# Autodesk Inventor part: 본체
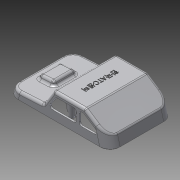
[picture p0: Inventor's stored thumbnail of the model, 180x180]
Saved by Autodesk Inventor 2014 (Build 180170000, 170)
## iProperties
Created: 2015-05
Part Number: 본체
Material: ABS 플라스틱
Document SubType Name: Modeling
Designer: Administrator
Density: 1.06 g/cm^3
Appearance: 매끄러움 - 흰색
Mass: 35.782 g
Surface Area: 333.401 cm^2
Volume: 33.7566 cm^3
Author: Administrator
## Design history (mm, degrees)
sketch "스케치1"
  geometry: L1 (61, 0)-(-61, 0); L2 (-61, 0)-(-61, 30); L3 (-61, 30)-(19, 30); L4 (19, 10.201)-(61, 8); L5 (61, 8)-(61, 0); L6 (19, 30)-(19, 10.201); 2 further points
  constraints: 12 end point, 2 parallel, 2 perpendicular, 1 coincident, 1 horizontal, 1 midpoint
  dimensions: "d0" = 122 distance of L1.end L1.start; "d2" = 30 distance of L1.end L2.end; "d4" = 3 deg angle of L1 L4; "d5" = 8 distance of L4.end L1.start; "d6" = 80 distance of L2.end L3.end
extrude "돌출1" new body sketch "스케치1" stored distance "d7" = 76; taper "d8" = 0 deg
sketch "스케치2"
  geometry: L1 (61, 0)-(61, 30) reference; L2 (61, 30)-(-19, 30) reference; L3 (31, 30)-(61, 10); 1 further point
  constraints: 2 end point, 2 point on line
  dimensions: "d9" = 20 vertical distance of L3.start L3.end; "d10" = 30 horizontal distance of L3.start L3.end
extrude "돌출2" cut sketch "스케치2" stored distance "d11" = 76; taper "d12" = 0 deg
sketch "스케치3"
  geometry: L1 (61, 10)-(31, 30) reference; L2 (-61, 0)-(61, 0) reference; L3 (61, 0)-(61, 10) reference; L4 (57.738, 12.175)-(61, 0); 1 further point
  constraints: 2 end point, 1 point on line
  dimensions: "d13" = 105 deg angle of L2 L4
extrude "돌출3" cut sketch "스케치3" stored distance "d14" = 76; taper "d15" = 0 deg
sketch "스케치4"
  geometry: L1 (31, 30)-(-19, 30) reference; L2 (-19, 30)-(-19, 10.201) reference; L3 (-19, 10.201)-(-61, 8) reference; L4 (-19, 10.201)-(-6.628, 30); 1 further point
  constraints: 2 end point, 1 point on line
  dimensions: "d16" = 125 deg angle of L3 L4
extrude "돌출4" cut sketch "스케치4" stored distance "d17" = 76; taper "d18" = 0 deg
sketch "스케치5"
  geometry: L1 (-19, 10.201)-(-61, 8) reference; L2 (-50, 8.576)-(-48.471, 13.576); L3 (-48.471, 13.576)-(-32.122, 14.625); L4 (-32.122, 14.625)-(-30, 9.625); 1 further point
  constraints: 6 end point, 2 point on line
  dimensions: "d19" = 70 deg angle of L1 L4; "d20" = 70 deg angle of L1 L2; "d21" = 20 horizontal distance of L4.end L2.start; "d22" = 5 vertical distance of L2.start L2.end; "d23" = 5 vertical distance of L3.end L4.end; "d24" = 11 horizontal distance of L1.end L2.start
extrude "돌출5" join sketch "스케치5" distance "d25" = 76; taper "d26" = 0 deg
sketch "스케치6"
  geometry: L1 (-30, 9.625)-(-32.122, 14.625) reference; L2 (-32.122, 14.625)-(-48.471, 13.576) reference; L3 (-48.471, 13.576)-(-50, 8.576) reference; L4 (-50, 8.576)-(-61, 8) reference; L5 (-50, 8.576)-(-30, 9.625); 1 further point
  constraints: 2 end point, 1 collinear
extrude "돌출6" cut sketch "스케치6" distance "d27" = 25; taper "d28" = 0 deg
sketch "스케치7"
  geometry: L1 (-19, 10.201)-(-61, 8) reference; L2 (-61, 8)-(-61, 0) reference; L3 (-61, 0)-(61, 0) reference; L4 (-61, 0)-(-58.826, 8.114); 1 further point
  constraints: 2 end point, 1 point on line
  dimensions: "d29" = 105 deg angle of L3 L4
extrude "돌출7" cut sketch "스케치7" stored distance "d30" = 25; taper "d31" = 0 deg
fillet "모깎기1" dims "d32" = 12
fillet "모깎기2" dims "d33" = 3
fillet "모깎기3" dims "d34" = 3
fillet "모깎기4" dims "d35" = 3
feature "쉘1" dims "d36" = 2
sketch "스케치8"
  geometry: L1 (-7.51, 28.59)-(-18.172, 11.526) reference; L2 (30.092, 30)-(-4.965, 30) reference; L3 (45.453, 20.365)-(31.756, 29.496) reference; L4 (-4.738, 23.59)-(-10.362, 14.59); L5 (-7.818, 10)-(17.77, 10); L6 (20.77, 13)-(20.77, 22); L7 (17.77, 25)-(-2.194, 25); L8 (23.986, 22)-(23.986, 13); L9 (26.986, 10)-(42.078, 10); L10 (26.986, 25)-(28.578, 25); L11 (30.242, 24.496)-(43.742, 15.496); A1 r 3 centre (-2.194, 22) between (-2.194, 25) and (-4.738, 23.59); A2 r 3 centre (-7.818, 13) between (-10.362, 14.59) and (-7.818, 10); A3 r 3 centre (17.77, 13) between (17.77, 10) and (20.77, 13); A4 r 3 centre (17.77, 22) between (20.77, 22) and (17.77, 25); A5 r 3 centre (26.986, 22) between (26.986, 25) and (23.986, 22); A6 r 3 centre (26.986, 13) between (23.986, 13) and (26.986, 10); A7 r 3 centre (42.078, 13) between (42.078, 10) and (43.742, 15.496); A8 r 3 centre (28.578, 22) between (30.242, 24.496) and (28.578, 25); 7 further points
  constraints: 16 end point, 16 point on circle, 16 tangent, 12 point on line, 8 centre point, 6 equal radius, 4 parallel, 3 perpendicular
  dimensions: "d37" = 5 distance between parallel lines of L4 L1; "d38" = 5 distance between parallel lines of L2 L7; "d39" = 34 distance of point (-13.23, 10) point (20.77, 10); "d40" = 15 distance of point (20.77, 10) point (20.77, 25); "d41" = 3 radius of A1; "d44" = 15 distance of point (23.986, 25) point (23.986, 10); "d45" = 28 distance of point (23.986, 10) point (51.986, 10); "d46" = 5 distance between parallel lines of L3 L11; "d47" = 5 distance between parallel lines of L2 L10; "d48" = 3 radius of A5
extrude "돌출8" cut sketch "스케치8" stored distance "d49" = 25; taper "d50" = 0 deg
node "작업 평면1"
sketch "스케치9"
  geometry: L1 (-23, 0)-(-19, 0); L2 (-12, 0)-(-8, 0); L3 (8, 0)-(12, 0); L4 (19, 0)-(23, 0); A1 r 2 centre (-10, 0) between (-8, 0) and (-12, 0); A2 r 2 centre (-21, 0) between (-19, 0) and (-23, 0); A3 r 2 centre (10, 0) between (12, 0) and (8, 0); A4 r 2 centre (21, 0) between (23, 0) and (19, 0); A5 r 2 centre (-21, 0) between (-23, 0) and (-19, 0); A6 r 2 centre (-10, 0) between (-12, 0) and (-8, 0); A7 r 2 centre (10, 0) between (8, 0) and (12, 0); A8 r 2 centre (21, 0) between (19, 0) and (23, 0); 5 further points
  constraints: 16 point on circle, 8 centre point, 8 end point, 4 coincident, 4 horizontal alignment, 4 midpoint, 3 collinear, 1 horizontal
  dimensions: "d52" = 4 diameter of A3; "d53" = 4 diameter of A4; "d54" = 4 diameter of A1; "d55" = 4 diameter of A2; "d56" = 10 distance of A3.centre point (0, 0); "d57" = 20 distance of A3.centre A1.centre; "d58" = 11 distance of A4.centre A3.centre; "d59" = 11 distance of A1.centre A2.centre
extrude "돌출9" join sketch "스케치9" stored distance "d60" = 25; taper "d61" = 0 deg
chamfer "모따기1" distance "d62" = 1; stored, may be unused: second distance "d63" = 2, angle "d64" = 45 deg
sketch "스케치10"
  geometry: L1 (0, 0)-(97.153, 0) reference; L2 (-10.353, -64)-(-10.353, -12) reference; L3 (0, -2)-(97.153, -2) reference; L4 (107.506, -12)-(107.506, -64) reference; L5 (97.153, -74)-(0, -74) reference; L6 (97.153, -1)-(0, -1); L7 (-11.353, -12)-(-11.353, -64); L8 (0, -75)-(97.153, -75); L9 (108.506, -64)-(108.506, -12); 5 further points; 4 other entities
  constraints: 8 end point, 7 parallel, 16 other
  dimensions: "d65" = 1 distance between parallel lines of L1 L6
extrude "돌출10" join sketch "스케치10" distance "d66" = 1; taper "d67" = 0 deg
sketch "스케치11"
  geometry: L1 (-12.423, -12)-(-12.423, -64) reference; C1 r 3 at (88.577, -38); C2 r 3 at (48.577, -16); C3 r 3 at (48.577, -60); C4 r 3 at (8.577, -38); 1 further point
  constraints: 4 centre point, 2 horizontal alignment, 2 vertical alignment
  dimensions: "d68" = 6 diameter of C1; "d69" = 6 diameter of C3; "d70" = 6 diameter of C2; "d71" = 6 diameter of C4; "d91" = 40 distance of C1.centre point (48.577, -38); "d92" = 40 distance of C4.centre point (48.577, -38); "d93" = 21 distance from line of C4.centre L1 (derived); "d94" = 22 distance of C3.centre point (48.577, -38); "d95" = 44 distance of C3.centre C2.centre
extrude "돌출11" join sketch "스케치11" stored distance "d72" = 1; taper "d73" = 4 deg
node "작업 평면2"
sketch "스케치12"
  geometry: L1 (-5, 23)-(5, 23); L2 (5, 23)-(5, 21); L3 (5, 21)-(-5, 21); L4 (-5, 21)-(-5, 23); L5 (-5, 23)-(5, 21); L6 (5, 23)-(-5, 21); L7 (44.982, 1)-(34.982, 1); L8 (34.982, 1)-(34.982, -1); L9 (34.982, -1)-(44.982, -1); L10 (44.982, -1)-(44.982, 1); L11 (44.982, 1)-(34.982, -1); L12 (34.982, 1)-(44.982, -1); L13 (-5, -21)-(5, -21); L14 (5, -21)-(5, -23); L15 (5, -23)-(-5, -23); L16 (-5, -23)-(-5, -21); L17 (-5, -21)-(5, -23); L18 (5, -21)-(-5, -23); L19 (-44.786, 1)-(-34.786, 1); L20 (-34.786, 1)-(-34.786, -1); L21 (-34.786, -1)-(-44.786, -1); L22 (-44.786, -1)-(-44.786, 1); L23 (-44.786, 1)-(-34.786, -1); L24 (-34.786, 1)-(-44.786, -1); C1 r 3 at (0, 22) reference; C2 r 3 at (40, 0) reference; C3 r 3 at (0, -22) reference; C4 r 3 at (-40, 0) reference; A1 r 5.028 centre (0, 22) between (4.965, 22.79) and (4.965, 21.21) reference; A2 r 5.028 centre (0, -22) between (4.965, -21.21) and (4.965, -22.79) reference; 3 further points; 2 other entities
  constraints: 48 end point, 8 midpoint, 8 parallel, 4 horizontal, 4 perpendicular, 2 vertical alignment, 2 other
  dimensions: "d75" = 10 distance of L2.end L3.end; "d76" = 2 distance of L1.end L2.end; "d77" = 10 distance of L8.end L9.end; "d78" = 2 distance of L7.end L8.end; "d79" = 10 distance of L14.end L15.end; "d80" = 2 distance of L13.end L14.end; "d81" = 10 distance of L20.end L21.end; "d82" = 2 distance of L19.end L20.end
extrude "돌출12" join sketch "스케치12" stored distance "d83" = 1; taper "d84" = 2.5 deg
sketch "스케치13"
  geometry: L1 (0, 0)-(-1.095, 25.103) reference; L2 (-11.476, 7.847)-(-0.813, 24.895) reference; L3 (0, 0)-(-3.694, 20.948); L4 (-4.589, 26.025)-(0.035, 26.025); L5 (-1.095, 25.103)-(-3.694, 20.948); L6 (-3.694, 20.948)-(-4.589, 26.025); 5 further points; 1 other entity
  constraints: 8 end point, 2 horizontal, 2 point on line, 1 coincident, 1 parallel, 1 other
  dimensions: "d85" = 100 deg angle of L3 L4
extrude "돌출13" join sketch "스케치13" stored distance "d86" = 1; taper "d87" = 0 deg
sketch "스케치14"
  geometry: L1 (1.95, 0)-(3.085, 26.025) reference; L2 (-8.015, 25.365)-(27.042, 25.365) reference; L3 (1.95, 0)-(6.539, 26.025); L4 (3.085, 26.025)-(6.539, 26.025); 1 further point
  constraints: 4 end point, 1 parallel
  dimensions: "d88" = 100 deg angle of L4 L3
extrude "돌출14" join sketch "스케치14" stored distance "d89" = 1; taper "d90" = 0 deg
sketch "스케치16"
  geometry: L1 (2.432, -15.957)-(0.983, -16.923) reference; L2 (1.736, 0)-(2.432, -15.957) reference; L3 (1.736, 0)-(0, 0) reference; L4 (1.736, 0)-(4.55, -15.957); L5 (2.432, -15.957)-(4.55, -15.957); L6 (2.432, -15.957)-(4.327, -14.692); 3 further points
  constraints: 6 end point, 2 coincident, 1 collinear, 1 parallel, 1 point on line
  dimensions: "d99" = 100 deg angle of L5 L4
extrude "돌출16" join sketch "스케치16" stored distance "d100" = 1; taper "d101" = 0 deg
sketch "스케치17"
  geometry: L1 (1.354, -9.892)-(-0.427, -9.778) reference; L2 (0, 0)-(-0.427, -9.778) reference; L3 (0, 0)-(-2.349, -9.655); L4 (-0.427, -9.778)-(-2.349, -9.655); 1 further point
  constraints: 4 end point, 1 collinear
  dimensions: "d102" = 100 deg angle of L3 L4
extrude "돌출17" join sketch "스케치17" stored distance "d103" = 1; taper "d104" = 0 deg
sketch "스케치18"
  geometry: L1 (2.425, -10.476)-(0.606, -10.36) reference; L2 (1.968, 0)-(2.425, -10.476) reference; L3 (1.968, 0)-(3.134, -10.522); L4 (2.425, -10.476)-(3.134, -10.522); 1 further point
  constraints: 4 end point, 1 collinear
  dimensions: "d105" = 100 deg angle of L4 L3
extrude "돌출18" join sketch "스케치18" stored distance "d106" = 1; taper "d107" = 0 deg
sketch "스케치20"
  geometry: L1 (-1.038, 23.787)-(0.861, 22.52) reference; L2 (0, 0)-(-1.038, 23.787) reference; L3 (0, 0)-(2.164, 0) reference; L4 (0, 0)-(-4.584, 25.995); L5 (-1.038, 23.787)-(-4.347, 25.995); L6 (-4.347, 25.995)-(-4.584, 25.995); 1 further point
  constraints: 6 end point, 1 collinear, 1 parallel
  dimensions: "d108" = 100 deg angle of L4 L6
extrude "돌출19" join sketch "스케치20" stored distance "d109" = 1; taper "d110" = 0 deg
sketch "스케치21"
  geometry: L1 (3.116, 10.48)-(1.974, 0.145) reference; L2 (1.974, 0.145)-(3.796, 10.48); L3 (3.116, 10.48)-(3.796, 10.48); 3 further points; 1 other entity
  constraints: 4 end point, 1 horizontal, 1 other
  dimensions: "d111" = 100 deg angle of L3 L2
extrude "돌출20" join sketch "스케치21" stored distance "d112" = 1; taper "d113" = 0 deg
sketch "스케치22"
  geometry: C1 r 3 at (0, 0) reference; C2 r 3 at (0, 44) reference; C3 r 3 at (40, 22) reference; C4 r 3 at (-40, 22) reference; 5 further points
  constraints: 4 coincident
hole "구멍1" sketch "스케치22" at (0, 44), (40, 22), (0, 0), (-40, 22) diameter "d114" = 3.242; stored, may be unused: countersink angle "d118" = 90 deg, drill point angle "d120" = 118 deg; dims "d115" = 9, "d116" = 19.05, "d117" = 4.775, "d119" = 11
sketch "스케치23"
  geometry: L1 (65.965, 61)-(65.965, 9) reference; 2 further points
  constraints: 1 horizontal alignment, 1 other
  dimensions: "d121" = 50 distance from line of L1 point (15.965, 35)
feature "엠보싱1" sketch "스케치23" dims "d122" = 0.5, "d123" = 0
node "솔리드1"
mirror "대칭1"
mirror "대칭2"
node "투영된 루프1"
node "투영된 루프2"
node "투영된 루프3"
node "투영된 루프4"
node "투영된 루프6"
node "투영된 루프7"
node "투영된 루프8"
other parameters: "d51" = -63, "d74" = 2
